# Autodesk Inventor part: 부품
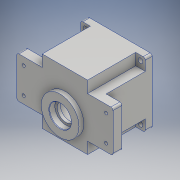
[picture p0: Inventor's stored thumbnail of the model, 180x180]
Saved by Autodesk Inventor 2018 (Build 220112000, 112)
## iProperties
Created: 2020-07
Part Number: 부품
Material: 알루미늄 6061
Document SubType Name: Modeling
Designer: Admin
Density: 2.7 g/cm^3
Appearance: 알루미늄 - 평지
Author: Admin
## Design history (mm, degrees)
sketch "스케치1"
  geometry: L1 (0, -65.8)-(0, 65.8) reference; L2 (-98, 0)-(98, 0) reference; L3 (33, 47)-(-33, 47); L4 (-33, 47)-(-33, 30); L5 (-33, 30)-(-70, 30); L6 (-70, 30)-(-70, -30); L7 (-70, -30)-(-33, -30); L8 (-33, -30)-(-33, -47); L9 (-33, -47)-(33, -47); L10 (33, -47)-(33, -30); L11 (33, -30)-(70, -30); L12 (70, -30)-(70, 30); L13 (70, 30)-(33, 30); L14 (33, 47)-(33, 30); 1 further point
  constraints: 24 end point, 8 perpendicular, 7 point on line, 1 horizontal, 3 other
  dimensions: "d0" = 140 distance between parallel lines of L6 L12; "d1" = 60 distance between parallel lines of L7 L5; "d2" = 66 distance of L3.start L3.end; "d3" = 17 distance of L3.end L4.end; "d4" = 17 distance of L7.end L8.end
extrude "돌출1" new body sketch "스케치1" distance "d5" = 13; taper "d6" = 0 deg
sketch "스케치2"
  geometry: L1 (-33, -47)-(33, -47) reference; L2 (33, -47)-(33, -30) reference; L3 (33, -30)-(70, -30) reference; L4 (70, -30)-(70, 30) reference; L5 (70, 30)-(33, 30) reference; L6 (33, 30)-(33, 47) reference; L7 (33, 47)-(-33, 47) reference; L8 (-33, 47)-(-33, 30) reference; L9 (-33, 30)-(-70, 30) reference; L10 (-70, 30)-(-70, -30) reference; L11 (-70, -30)-(-33, -30) reference; L12 (-33, -30)-(-33, -47) reference; L13 (-47, -47)-(47, -47); L14 (47, -47)-(47, 47); L15 (47, 47)-(-47, 47); L16 (-47, 47)-(-47, -47); L17 (-47, -47)-(47, 47); L18 (47, -47)-(-47, 47); 1 further point
  constraints: 12 end point, 2 midpoint, 2 parallel, 1 horizontal, 1 perpendicular
  dimensions: "d7" = 94 distance of L14.end L15.end; "d8" = 94 distance of L13.end L14.end
extrude "돌출2" join sketch "스케치2" distance "d9" = 67; taper "d10" = 0 deg
sketch "스케치3"
  geometry: L1 (-33, 47)-(33, 47) reference; L2 (-33, 30)-(-33, 47) reference; L3 (-70, 30)-(-33, 30) reference; L4 (-70, -30)-(-70, 30) reference; L5 (-33, -30)-(-70, -30) reference; L6 (-33, -47)-(-33, -30) reference; L7 (33, -47)-(-33, -47) reference; L8 (33, -30)-(33, -47) reference; L9 (70, -30)-(33, -30) reference; L10 (70, 30)-(70, -30) reference; L11 (33, 30)-(70, 30) reference; L12 (33, 47)-(33, 30) reference; L13 (33, 47)-(47, 47) reference; L14 (47, 47)-(47, 30) reference; L15 (47, -30)-(47, -47) reference; L16 (47, -47)-(33, -47) reference; L17 (-33, -47)-(-47, -47) reference; L18 (-47, -47)-(-47, -30) reference; L19 (-47, 30)-(-47, 47) reference; L20 (-47, 47)-(-33, 47) reference; L21 (47, -47)-(-47, -47) reference; L22 (-47, -47)-(-33, -47); L23 (-33, -47)-(-33, -30); L24 (-33, -30)-(-47, -30); L25 (-47, -30)-(-47, -47); L26 (-47, 30)-(-33, 30) reference; L27 (-47, 30)-(-33, 30); L28 (-33, 30)-(-33, 47); L29 (-33, 47)-(-47, 47); L30 (-47, 47)-(-47, 30); L31 (33, 47)-(33, 30) reference; L32 (33, 30)-(47, 30); L33 (47, 30)-(47, 47); L34 (47, 47)-(33, 47); L35 (33, 47)-(33, 30); L36 (33, -47)-(-33, -47) reference; L37 (33, -47)-(47, -47); L38 (47, -47)-(47, -30); L39 (47, -30)-(33, -30); L40 (33, -30)-(33, -47); 1 further point
  constraints: 32 end point, 8 parallel, 4 horizontal, 4 perpendicular
extrude "돌출3" cut sketch "스케치3" distance "d11" = 70; taper "d12" = 0 deg
sketch "스케치8"
  geometry: L1 (98, 0)-(-98, 0) reference; L2 (0, 65.8)-(0, -65.8) reference; C1 r 43 at (0, 0); 1 further point
  constraints: 1 centre point, 1 coincident
  dimensions: "d28" = 86 diameter of C1
extrude "돌출8" cut sketch "스케치8" distance "d29" = 9; taper "d30" = 0 deg
sketch "스케치9"
  geometry: C1 r 43 at (0, 0) reference; C2 r 40 at (0, 0); 1 further point
  constraints: 1 centre point, 1 coincident
  dimensions: "d31" = 80 diameter of C2
extrude "돌출9" cut sketch "스케치9" distance "d32" = 55; taper "d33" = 0 deg
sketch "스케치13"
  geometry: L1 (0, 65.8)-(0, -65.8) reference; L2 (98, 0)-(-98, 0) reference; L3 (-35.778, 3.994)-(-39.8, 3.994); L4 (-35.778, -3.994)-(-39.8, -3.994); C1 r 40 at (0, 0) reference; C2 r 43 at (0, 0) reference; A1 r 40 centre (0, 0) between (-39.8, 3.994) and (-39.8, -3.994) reference; A2 r 36 centre (0, 0) between (-36, 0) and (-35.778, 3.994); A3 r 4 centre (-36, 0) between (-36.222, -3.994) and (-36.222, 3.994); A4 r 40 centre (0, 0) between (-39.8, 3.994) and (-39.8, -3.994); 1 further point
  constraints: 11 point on circle, 4 end point, 3 centre point, 3 point on line, 2 coincident, 2 horizontal
  dimensions: "d45" = 72 diameter of A2; "d46" = 8 diameter of A3
extrude "돌출13" join sketch "스케치13" stored distance "d47" = 7; taper "d48" = 0 deg
sketch "스케치14"
  geometry: L1 (0, 65.8)-(0, -65.8) reference; L2 (98, 0)-(-98, 0) reference; L3 (-35.778, 3.994)-(-39.8, 3.994) reference; L4 (-39.8, -3.994)-(-35.778, -3.994) reference; C1 r 43 at (0, 0) reference; A1 r 40 centre (0, 0) between (-39.8, -3.994) and (-39.8, 3.994) reference; A2 r 4 centre (-36, 0) between (-35.778, -3.994) and (-35.778, 3.994) reference; 2 further points
  constraints: 1 coincident
hole "구멍1" sketch "스케치14" at (-36, 0) diameter "d49" = 3.242; stored, may be unused: countersink angle "d53" = 90 deg, drill point angle "d55" = 118 deg; dims "d50" = 7, "d51" = 4, "d52" = 2, "d54" = 9
sketch "스케치24"
  geometry: L1 (0, 65.8)-(0, -65.8) reference; L2 (98, 0)-(-98, 0) reference; L3 (70, -30)-(70, 30) reference; C1 r 5 at (60, -19); C2 r 5 at (60, 19); C3 r 5 at (-60, -19); C4 r 5 at (-60, 19); 5 further points
  constraints: 4 centre point, 4 symmetric about line, 2 coincident, 2 other
  dimensions: "d67" = 38 distance of point (60, -19) point (60, 19); "d68" = 10 distance from line of L3 point (60, -19); "d69" = 10 distance from line of L3 point (60, 19); "d70" = 19 distance from line of L2 point (60, -19); "d71" = 10 diameter of C1; "d72" = 10 diameter of C2
extrude "돌출17" cut sketch "스케치24" distance "d73" = 5; taper "d74" = 0 deg
sketch "스케치25"
  geometry: L1 (60, 84.8)-(60, -46.8) reference; C1 r 5 at (120, 0) reference; C2 r 5 at (120, 38) reference; C3 r 5 at (0, 38) reference; C4 r 5 at (0, 0) reference; C5 r 2.25 at (120, 0); C6 r 2.25 at (120, 38); C7 r 2.25 at (0, 0); C8 r 2.25 at (0, 38); 1 further point
  constraints: 4 centre point, 2 coincident, 2 symmetric about line, 2 other
  dimensions: "d75" = 4.5 diameter of C5; "d76" = 4.5 diameter of C6
extrude "돌출18" cut sketch "스케치25" extent not by distance; stored distance "d77" = 0; taper "d78" = 0 deg
sketch "스케치26"
  geometry: L1 (-98, 0)-(98, 0) reference; L2 (0, 65.8)-(0, -65.8) reference; L3 (-47, 47)-(47, 47) reference; L4 (47, 47)-(47, -47) reference; L5 (47, -47)-(-47, -47) reference; L6 (-47, -47)-(-47, 47) reference; L7 (40, -40)-(-40, -40); L8 (-40, -40)-(-40, 40); L9 (-40, 40)-(40, 40); L10 (40, 40)-(40, -40); L11 (40, -40)-(-40, 40); L12 (-40, -40)-(40, 40); C1 r 43 at (0, 0) reference; C2 r 3.5 at (40, -40); C3 r 3.5 at (40, 40); C4 r 3.5 at (-40, -40); C5 r 3.5 at (-40, 40); 1 further point
  constraints: 12 end point, 4 centre point, 3 symmetric about line, 2 midpoint, 2 parallel, 1 coincident, 1 horizontal, 1 perpendicular, 3 other
  dimensions: "d79" = 80 distance of L7.end L8.end; "d80" = 80 distance of L8.end L9.end; "d81" = 7 diameter of C2
extrude "돌출19" cut sketch "스케치26" extent not by distance; stored distance "d82" = 5; taper "d83" = 0 deg
sketch "스케치27"
  geometry: L1 (-14, 80)-(80, 80) reference; 2 further points
  constraints: 1 other
  dimensions: "d84" = 40 distance from line of L1 point (32.773, 40)
feature "엠보싱1" sketch "스케치27" dims "d0" = 140, "d1" = 60, "d2" = 66, "d3" = 17, "d4" = 17, "d85" = 0.5, "d86" = 0
fillet "모깎기1" dims "d87" = 3
chamfer "모따기1" distance "d89" = 1; stored, may be unused: second distance "d90" = 2, angle "d91" = 45 deg
sketch "스케치28"
  geometry: L1 (35.778, 3.994)-(39.8, 3.994) reference; L2 (-39.8, 3.994)-(-35.778, 3.994) reference; L3 (-35.778, -3.994)-(-39.8, -3.994) reference; L4 (39.8, -3.994)-(35.778, -3.994) reference; L5 (0, 65.8)-(0, -65.8) reference; L6 (98, 0)-(-98, 0) reference; C1 r 11 at (0, -20); A1 r 40 centre (0, 0) between (39.8, 3.994) and (-39.8, 3.994) reference; A2 r 4 centre (-36, 0) between (-35.778, -3.994) and (-35.778, 3.994) reference; A3 r 40 centre (0, 0) between (-39.8, -3.994) and (39.8, -3.994) reference; A4 r 4 centre (36, 0) between (35.778, 3.994) and (35.778, -3.994) reference; 1 further point
  constraints: 1 centre point, 1 point on line
  dimensions: "d98" = 22 diameter of C1; "d99" = 20 distance from line of C1.centre L6
extrude "돌출20" cut sketch "스케치28" distance "d100" = 7; taper "d101" = 0 deg
sketch "스케치29"
  geometry: L1 (0, 65.8)-(0, -65.8) reference; L2 (-98, 0)-(98, 0) reference; C1 r 27.5 at (0, -11); 1 further point
  constraints: 1 centre point, 1 point on line
  dimensions: "d104" = 55 diameter of C1; "d105" = 11 distance from line of L2 C1.centre
extrude "돌출21" join sketch "스케치29" distance "d106" = 7; taper "d107" = 0 deg
sketch "스케치30"
  geometry: C1 r 11 at (0, 0) reference; C2 r 9.5 at (0, 0); 1 further point
  constraints: 1 centre point, 1 coincident
  dimensions: "d108" = 19 diameter of C2
extrude "돌출22" cut sketch "스케치30" distance "d109" = 3; taper "d110" = 0 deg
sketch "스케치32"
  geometry: C1 r 27.5 at (0, 0) reference; C2 r 16 at (0, 0); 1 further point
  constraints: 1 centre point, 1 coincident
  dimensions: "d111" = 32 diameter of C2
extrude "돌출23" cut sketch "스케치32" distance "d112" = 8.3; taper "d113" = 0 deg
sketch "스케치33"
  geometry: C1 r 16 at (0, 0) reference; C2 r 12.5 at (0, 0); 1 further point
  constraints: 1 centre point, 1 coincident
  dimensions: "d114" = 25 diameter of C2
extrude "돌출24" cut sketch "스케치33" distance "d115" = 4.7; taper "d116" = 0 deg
sketch "스케치34"
  geometry: C1 r 12.5 at (0, 0) reference; C2 r 17.5 at (0, 0); 1 further point
  constraints: 1 centre point, 1 coincident
  dimensions: "d117" = 35 diameter of C2
extrude "돌출25" cut sketch "스케치34" distance "d118" = 10; taper "d119" = 0 deg
chamfer "모따기4" distance "d120" = 0.8; stored, may be unused: second distance "d121" = 2, angle "d122" = 30 deg
fillet "모깎기3" dims "d126" = 3
sketch "스케치36"
  geometry: L1 (35.778, 3.994)-(39.8, 3.994) reference; L2 (-39.8, 3.994)-(-35.778, 3.994) reference; L3 (-35.778, -3.994)-(-39.8, -3.994) reference; L4 (39.8, -3.994)-(35.778, -3.994) reference; C1 r 17.5 at (0, 11) reference; C2 r 11 at (0, -20) reference; A1 r 40 centre (0, 0) between (39.8, 3.994) and (-39.8, 3.994) reference; A2 r 4 centre (-36, 0) between (-35.778, -3.994) and (-35.778, 3.994) reference; A3 r 40 centre (0, 0) between (-39.8, -3.994) and (39.8, -3.994) reference; A4 r 4 centre (36, 0) between (35.778, 3.994) and (35.778, -3.994) reference; A5 r 21 centre (0, 11) between (8.978, -7.984) and (-8.978, -7.984); A6 r 15 centre (0, -20) between (-8.978, -7.984) and (8.978, -7.984); 1 further point
  constraints: 4 point on circle, 2 centre point, 2 coincident
  dimensions: "d129" = 42 diameter of A5; "d130" = 30 diameter of A6
extrude "돌출26" join sketch "스케치36" distance "d131" = 7; taper "d132" = 0 deg
chamfer "모따기6" distance "d133" = 1; stored, may be unused: second distance "d134" = 2, angle "d135" = 45 deg
node "솔리드1"
mirror "미러1"
node "투영된 루프1"
node "투영된 루프2"
node "투영된 루프10"
node "투영된 루프11"
node "투영된 루프15"
node "투영된 루프16"
node "투영된 루프17"
node "투영된 루프19"
node "투영된 루프20"
node "투영된 루프21"
node "투영된 루프23"
other parameters: "d127" = 42
